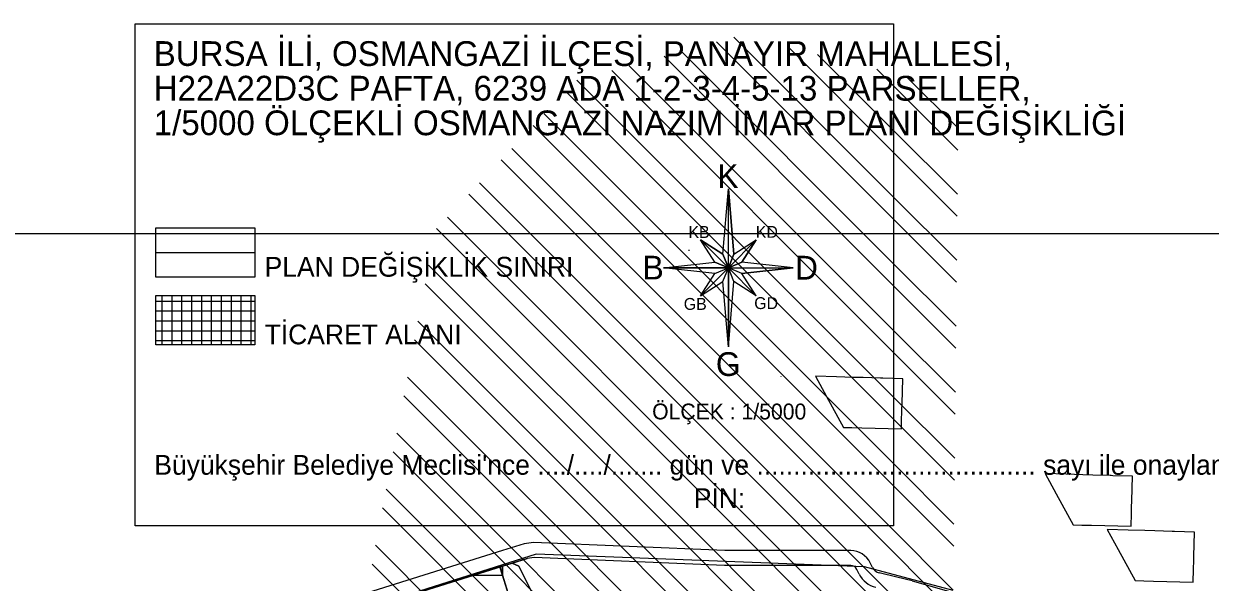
# Model space of a CAD drawing. Extents: x 409341 to 428634, y 4447481 to 4463281.
# Drawn here: x 420364 to 421563, y 4458529 to 4459094 of the extents above; entities that cross this region are included whole.
import ezdxf

# ---------------------------------------------------------------- set-up
doc = ezdxf.new("R2010")
doc.units = 0
for name, color, linetype in [('ADA', 7, 'Continuous'), ('ADAKENARI', 7, 'Continuous'), ('Default', 7, 'Continuous'), ('LJ_KUTU', 7, 'Continuous'), ('LJ_KUZEY', 7, 'Continuous'), ('LJ_SEMBOL', 7, 'Continuous'), ('LJ_YAZI', 7, 'Continuous'), ('OSB', 7, 'Continuous'), ('PL_AYA_PARK_DINLENME', 7, 'Continuous'), ('PL_K_TALI_IS_MRK', 7, 'Continuous'), ('PL_KON_ONE_250', 7, 'Continuous'), ('SN_ plan değişikliği', 7, 'Continuous'), ('SN_TR_SIVILASMA', 7, 'Continuous'), ('TR_ORTAGELISME', 7, 'Continuous'), ('TR_PARKALANI', 7, 'Continuous'), ('TR_TALIISMERK', 7, 'Continuous'), ('TR_YUKSEKYOGUNKONUT', 7, 'Continuous')]:
    doc.layers.add(name, color=color, linetype=linetype)

# ---------------------------------------------------------------- blocks, each defined once
blk = doc.blocks.new('POINT_DISPLAY')
at = {"layer": 'Default'}
blk.add_line((0, 0), (0, 0), dxfattribs=at)

msp = doc.modelspace()

# ---------------------------------------------------------------- linework, layer by layer
at = {"layer": 'ADA'}
msp.add_line((420844.7, 4458545.3), (420871.2, 4458460.8), dxfattribs=at)
at = {"layer": 'ADAKENARI'}
for p, q in [((420869.2, 4458568.3), (420847.5, 4458561.5)), ((420878.9, 4458569.6), (420869.2, 4458568.3)), ((421072.3, 4458561.4), (420878.9, 4458569.6)), ((420847.5, 4458561.5), (420577.1, 4458477)), ((420847.5, 4458545.8), (420872.4, 4458553.6)), ((420879.6, 4458554.5), (420872.4, 4458553.6)), ((421071.9, 4458546.4), (420879.6, 4458554.5)), ((421199.4, 4458561.4), (421072.3, 4458561.4)), ((420732.5, 4458509.8), (420847.5, 4458545.8)), ((421199.4, 4458546.4), (421071.9, 4458546.4)), ((421208, 4458537.7), (421205.7, 4458542.5)), ((421221.5, 4458544.3), (421219.2, 4458549.1)), ((421246.1, 4458534.7), (421228.2, 4458539)), ((421261.7, 4458531), (421246.1, 4458534.7)), ((421261.7, 4458531), (421303.1, 4458519))]:
    msp.add_line(p, q, dxfattribs=at)
for centre, radius, start, end in [((421199.4, 4458539.4), 22, 26.131, 90), ((421199.4, 4458539.4), 7, 26.131, 90), ((421230.5, 4458548.7), 10, 206.131, 256.6075), ((421230.5, 4458548.7), 25, 206.131, 256.6075)]:
    msp.add_arc(centre, radius, start, end, dxfattribs=at)
at = {"layer": 'Default'}
msp.add_lwpolyline([(428634.4, 4458881.4), (409341.5, 4458881.4)], dxfattribs=at)
for points in [[(421163.7, 4458737.6), (421174.9, 4458717.1), (421180.6, 4458706.8), (421192, 4458685.9), (421200.7, 4458685.7), (421210.7, 4458685.4), (421250.6, 4458684.5), (421250.7, 4458685.7), (421250.9, 4458696.3), (421251, 4458698.9), (421251.2, 4458704.7), (421251.3, 4458709), (421251.4, 4458710.2), (421252.2, 4458735), (421232, 4458735.6), (421230.5, 4458735.6), (421229.4, 4458735.7), (421211.9, 4458736.2), (421201.9, 4458736.5), (421185, 4458737)], [(421395.9, 4458639.2), (421407.1, 4458618.7), (421412.8, 4458608.4), (421424.3, 4458587.4), (421433, 4458587.2), (421442.9, 4458587), (421482.9, 4458586), (421482.9, 4458587.3), (421483.2, 4458597.9), (421483.3, 4458600.5), (421483.4, 4458606.3), (421483.6, 4458610.6), (421483.6, 4458611.7), (421484.4, 4458636.5), (421464.2, 4458637.1), (421462.8, 4458637.2), (421461.6, 4458637.2), (421444.1, 4458637.8), (421434.1, 4458638.1), (421417.2, 4458638.6)], [(421458.5, 4458582.9), (421469.7, 4458562.4), (421475.4, 4458552), (421486.9, 4458531.1), (421495.6, 4458530.9), (421505.5, 4458530.7), (421545.5, 4458529.7), (421545.5, 4458530.9), (421545.8, 4458541.5), (421545.9, 4458544.1), (421546.1, 4458550), (421546.2, 4458554.2), (421546.2, 4458555.4), (421547, 4458580.2), (421526.8, 4458580.8), (421525.4, 4458580.9), (421524.2, 4458580.9), (421506.7, 4458581.4), (421496.7, 4458581.7), (421479.8, 4458582.2)]]:
    msp.add_lwpolyline(points, close=True, dxfattribs=at)
at = {"layer": 'LJ_KUTU'}
for p, q in [((420497, 4458887.6), (420597, 4458887.6)), ((420497, 4458837.6), (420497, 4458887.6)), ((420597, 4458887.6), (420597, 4458837.6)), ((420597, 4458837.6), (420497, 4458837.6)), ((420497, 4458819.3), (420597, 4458819.3)), ((420497, 4458769.3), (420497, 4458819.3)), ((420597, 4458819.3), (420597, 4458769.3)), ((420597, 4458769.3), (420497, 4458769.3))]:
    msp.add_line(p, q, dxfattribs=at)
at = {"layer": 'LJ_SEMBOL'}
for p, q in [((421070.1, 4458860.8), (421075.8, 4458927)), ((421081.4, 4458860.8), (421075.8, 4458927)), ((421075.8, 4458847.1), (421047.5, 4458875.4)), ((421070.1, 4458860.8), (421047.5, 4458875.4)), ((421062.1, 4458852.8), (421047.5, 4458875.4)), ((421075.8, 4458847.1), (421104, 4458875.4)), ((421081.4, 4458860.8), (421104, 4458875.4)), ((421089.4, 4458852.8), (421104, 4458875.4)), ((421010.2, 4458847.1), (421062.1, 4458852.8)), ((421075.8, 4458847.1), (421062.1, 4458852.8)), ((421075.8, 4458847.1), (421070.1, 4458860.8)), ((421075.8, 4458847.1), (421081.4, 4458860.8)), ((421075.8, 4458847.1), (421089.4, 4458852.8)), ((421141.4, 4458847.1), (421089.4, 4458852.8)), ((421010.2, 4458847.1), (421075.8, 4458847.1)), ((421062.1, 4458841.5), (421010.2, 4458847.1)), ((421047.5, 4458818.9), (421075.8, 4458847.1)), ((421047.5, 4458818.9), (421062.1, 4458841.5)), ((421062.1, 4458841.5), (421075.8, 4458847.1)), ((421070.1, 4458833.5), (421075.8, 4458847.1)), ((421075.8, 4458847.1), (421141.4, 4458847.1)), ((421075.8, 4458767.2), (421075.8, 4458847.1)), ((421104, 4458818.9), (421075.8, 4458847.1)), ((421089.4, 4458841.5), (421075.8, 4458847.1)), ((421081.4, 4458833.5), (421075.8, 4458847.1)), ((421089.4, 4458841.5), (421141.4, 4458847.1)), ((421104, 4458818.9), (421089.4, 4458841.5)), ((421047.5, 4458818.9), (421070.1, 4458833.5)), ((421075.8, 4458767.2), (421070.1, 4458833.5)), ((421075.8, 4458767.2), (421081.4, 4458833.5)), ((421104, 4458818.9), (421081.4, 4458833.5))]:
    msp.add_line(p, q, dxfattribs=at)
for points in [[(421075.8, 4458927), (421081.4, 4458860.8), (421075.8, 4458847.1)], [(421047.5, 4458875.4), (421070.1, 4458860.8), (421075.8, 4458847.1)], [(421104, 4458875.4), (421089.4, 4458852.8), (421075.8, 4458847.1)], [(421062.1, 4458852.8), (421075.8, 4458847.1), (421010.2, 4458847.1)], [(421075.8, 4458847.1), (421047.5, 4458818.9), (421062.1, 4458841.5)], [(421075.8, 4458847.1), (421075.8, 4458767.2), (421070.1, 4458833.5)], [(421075.8, 4458847.1), (421141.4, 4458847.1), (421089.4, 4458841.5)], [(421075.8, 4458847.1), (421104, 4458818.9), (421081.4, 4458833.5)]]:
    msp.add_lwpolyline(points, close=True, dxfattribs=at)
at = {"layer": 'LJ_YAZI'}
msp.add_lwpolyline([(420476.1, 4459093.8), (421242.8, 4459093.8), (421242.8, 4458586.4), (420476.1, 4458586.4)], close=True, dxfattribs=at)
msp.add_lwpolyline([(420476.1, 4459093.8), (421242.8, 4459093.8), (421242.8, 4458586.4), (420476.1, 4458586.4)], close=True, dxfattribs=at)
msp.add_lwpolyline([(420476.1, 4459093.8), (421242.8, 4459093.8), (421242.8, 4458586.4), (420476.1, 4458586.4)], close=True, dxfattribs=at)
at = {"layer": 'OSB'}
msp.add_lwpolyline([(421303.1, 4458521), (421213.4, 4458545), (420881.6, 4458557.8), (420391.6, 4458402.7)], dxfattribs=at)
at = {"layer": 'PL_AYA_PARK_DINLENME'}
for p, q in [((420847.5, 4458545.8), (420844.9, 4458545)), ((420844.9, 4458545), (420847.5, 4458536.5)), ((420857.1, 4458548.8), (420847.5, 4458545.8)), ((420864.1, 4458545.8), (420857.1, 4458548.8)), ((420899.2, 4458474.8), (420864.1, 4458545.8)), ((420847.5, 4458536.5), (420871.2, 4458460.8))]:
    msp.add_line(p, q, dxfattribs=at)
for points in [[(420847.5, 4458545.8), (420847.5, 4458536.5)], [(420847.5, 4458536.5), (420847.5, 4458545.8)]]:
    msp.add_lwpolyline(points, dxfattribs=at)
at = {"layer": 'PL_K_TALI_IS_MRK'}
msp.add_lwpolyline([(420497, 4458819.3), (420597, 4458819.3), (420597, 4458769.3), (420497, 4458769.3)], close=True, dxfattribs=at)
at = {"layer": 'PL_KON_ONE_250'}
msp.add_line((421208, 4458537.7), (421205.7, 4458542.5), dxfattribs=at)
for points in [[(421199.4, 4458546.4), (421071.9, 4458546.4), (420879.6, 4458554.5), (420872.4, 4458553.6), (420857.1, 4458548.8), (420864.1, 4458545.8), (420899.2, 4458474.8), (420904.7, 4458463.7), (420914.6, 4458445.6)], [(420677.2, 4458364.6), (420677.3, 4458364.3), (420677.6, 4458363.4), (420703.7, 4458376.7), (420723.4, 4458386.7), (420743, 4458396.7), (420761.2, 4458405.9), (420784, 4458417.5), (420871.2, 4458460.8), (420847.5, 4458536.5), (420844.9, 4458545), (420732.5, 4458509.8), (420643.4, 4458482), (420659.5, 4458427.9), (420675.6, 4458370.4), (420677.2, 4458364.6)]]:
    msp.add_lwpolyline(points, dxfattribs=at)
for centre, radius, start, end in [((421199.4, 4458539.4), 7, 26.131, 90), ((421230.5, 4458548.7), 25, 206.131, 256.6075)]:
    msp.add_arc(centre, radius, start, end, dxfattribs=at)
at = {"layer": 'SN_ plan değişikliği'}
msp.add_line((420497, 4458862.6), (420597, 4458862.6), dxfattribs=at)
at = {"layer": 'SN_TR_SIVILASMA'}
for p, q in [((421242.8, 4458896.2), (421063.6, 4459075.4)), ((421242.8, 4458918.7), (421081.3, 4459080.3)), ((421242.8, 4458963.6), (421136.1, 4459070.3)), ((421242.8, 4458828.9), (421010.7, 4459061)), ((421242.8, 4458851.3), (421028.4, 4459065.8)), ((421242.8, 4458986), (421166, 4459062.8)), ((421242.8, 4458761.5), (420957.8, 4459046.5)), ((421242.8, 4458784), (420975.5, 4459051.3)), ((421242.8, 4459030.9), (421225.9, 4459047.8)), ((421242.8, 4458716.6), (420922.6, 4459036.9)), ((421308, 4458988.2), (421255.9, 4459040.3)), ((421242.8, 4458694.2), (420911.2, 4459025.8)), ((421307.8, 4458966), (421242.8, 4459030.9)), ((421242.8, 4458649.3), (420889.5, 4459002.7)), ((421242.8, 4458626.8), (420878.6, 4458991.1)), ((421307.3, 4458921.5), (421242.8, 4458986)), ((421238.3, 4458586.4), (420856.9, 4458967.9)), ((421307.1, 4458899.3), (421242.8, 4458963.6)), ((421215.9, 4458586.4), (420846, 4458956.3)), ((421171, 4458586.4), (420824.3, 4458933.1)), ((421148.5, 4458586.4), (420813.4, 4458921.5)), ((421306.6, 4458854.9), (421242.8, 4458918.7)), ((421103.6, 4458586.4), (420791.7, 4458898.4)), ((421306.4, 4458832.7), (421242.8, 4458896.2)), ((421081.2, 4458586.4), (420780.8, 4458886.8)), ((421036.3, 4458586.4), (420772.7, 4458850)), ((421305.9, 4458788.2), (421242.8, 4458851.3)), ((421013.8, 4458586.4), (420769.2, 4458831.1)), ((421305.7, 4458766), (421242.8, 4458828.9)), ((420968.9, 4458586.4), (420762, 4458793.3)), ((420968.9, 4458586.4), (420762, 4458793.3)), ((421305.2, 4458721.6), (421242.8, 4458784)), ((420946.5, 4458586.4), (420758.4, 4458774.5)), ((420946.5, 4458586.4), (420758.4, 4458774.5)), ((421305, 4458699.4), (421242.8, 4458761.5)), ((420901.6, 4458586.4), (420751.3, 4458736.7)), ((420879.1, 4458586.4), (420747.7, 4458717.8)), ((421304.5, 4458654.9), (421242.8, 4458716.6)), ((421304.3, 4458632.7), (421242.8, 4458694.2)), ((420822.7, 4458598), (420740.6, 4458680.1)), ((420800.2, 4458598), (420737, 4458661.2)), ((421303.8, 4458588.3), (421242.8, 4458649.3)), ((421303.6, 4458566), (421242.8, 4458626.8)), ((420755.3, 4458598), (420729.9, 4458623.4)), ((420732.9, 4458598), (420726.3, 4458604.5)), ((420744.4, 4458586.4), (420732.9, 4458598)), ((420766.9, 4458586.4), (420755.3, 4458598)), ((420811.8, 4458586.4), (420800.2, 4458598)), ((420834.2, 4458586.4), (420822.7, 4458598)), ((420847.5, 4458483.3), (420744.4, 4458586.4)), ((420847.5, 4458505.8), (420766.9, 4458586.4)), ((420847.5, 4458550.7), (420811.8, 4458586.4)), ((420847.5, 4458573.2), (420834.2, 4458586.4)), ((421299.4, 4458166.1), (420879.1, 4458586.4)), ((421299.7, 4458188.3), (420901.6, 4458586.4)), ((421300.1, 4458232.8), (420946.5, 4458586.4)), ((421300.1, 4458232.8), (420946.5, 4458586.4)), ((421300.4, 4458255), (420968.9, 4458586.4)), ((421300.4, 4458255), (420968.9, 4458586.4)), ((421300.8, 4458299.4), (421013.8, 4458586.4)), ((421301.1, 4458321.6), (421036.3, 4458586.4)), ((421301.5, 4458366.1), (421081.2, 4458586.4)), ((421301.8, 4458388.3), (421103.6, 4458586.4)), ((421302.2, 4458432.7), (421148.5, 4458586.4)), ((421302.5, 4458454.9), (421171, 4458586.4)), ((421302.9, 4458499.4), (421215.9, 4458586.4)), ((421303.1, 4458521.6), (421238.3, 4458586.4)), ((420847.5, 4458438.4), (420719.1, 4458566.8)), ((420976.9, 4458443.7), (420847.5, 4458573.2)), ((420847.5, 4458416), (420715.6, 4458547.9)), ((420953.8, 4458444.4), (420847.5, 4458550.7))]:
    msp.add_line(p, q, dxfattribs=at)
at = {"layer": 'TR_ORTAGELISME'}
for p, q in [((421208, 4458537.7), (421205.7, 4458542.5)), ((420818.3, 4458536.7), (420847.4, 4458536.7))]:
    msp.add_line(p, q, dxfattribs=at)
msp.add_lwpolyline([(421199.4, 4458546.4), (421071.9, 4458546.4), (420879.6, 4458554.5), (420872.4, 4458553.6), (420857.1, 4458548.8), (420864.1, 4458545.8), (420899.2, 4458474.8), (420904.7, 4458463.7), (420914.6, 4458445.6)], dxfattribs=at)
for centre, radius, start, end in [((421199.4, 4458539.4), 7, 26.131, 90), ((421230.5, 4458548.7), 25, 206.131, 256.6075)]:
    msp.add_arc(centre, radius, start, end, dxfattribs=at)
at = {"layer": 'TR_TALIISMERK'}
for p, q in [((420503.4, 4458769.3), (420503.4, 4458819.3)), ((420513.4, 4458769.3), (420513.4, 4458819.3)), ((420523.4, 4458769.3), (420523.4, 4458819.3)), ((420533.4, 4458769.3), (420533.4, 4458819.3)), ((420543.4, 4458769.3), (420543.4, 4458819.3)), ((420553.4, 4458769.3), (420553.4, 4458819.3)), ((420563.4, 4458769.3), (420563.4, 4458819.3)), ((420573.4, 4458769.3), (420573.4, 4458819.3)), ((420583.4, 4458769.3), (420583.4, 4458819.3)), ((420593.4, 4458769.3), (420593.4, 4458819.3)), ((420497, 4458813.6), (420597, 4458813.6)), ((420497, 4458803.6), (420597, 4458803.6)), ((420497, 4458793.6), (420597, 4458793.6)), ((420497, 4458783.6), (420597, 4458783.6)), ((420497, 4458773.6), (420597, 4458773.6))]:
    msp.add_line(p, q, dxfattribs=at)
at = {"layer": 'TR_YUKSEKYOGUNKONUT'}
for p, q in [((421036, 4458864.2), (421036, 4458865.2)), ((421129, 4458737.1), (421129, 4458737.3))]:
    msp.add_line(p, q, dxfattribs=at)

# ---------------------------------------------------------------- block references
at = {"layer": 'TR_PARKALANI', "xscale": 0.1, "yscale": 0.10000000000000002}
for p in [(420856.4, 4458546.4), (420852.8, 4458539.9), (420853.8, 4458531.8), (420857.5, 4458538.4), (420863, 4458535.2)]:
    msp.add_blockref('POINT_DISPLAY', p, dxfattribs=at)

# ---------------------------------------------------------------- texts
at = {"layer": 'LJ_KUZEY'}
msp.add_text('ÖLÇEK : 1/5000', height=16, rotation=359.9901, dxfattribs=at).set_placement((420998.7, 4458694))
at = {"layer": 'LJ_SEMBOL'}
for s, height, p in [('K', 24, (421064.6, 4458927.9)), ('KB', 12, (421035.4, 4458877.4)), ('KD', 12, (421103.5, 4458877.5)), ('B', 24, (420989, 4458835.4)), ('D', 24, (421143.1, 4458835.3)), ('GB', 12, (421030.7, 4458804.7)), ('GD', 12, (421101.9, 4458805.5)), ('G', 24, (421063.1, 4458737.9))]:
    msp.add_text(s, height=height, rotation=359.9901, dxfattribs=at).set_placement(p)
at = {"layer": 'LJ_YAZI'}
for s, p in [('BURSA İLİ, OSMANGAZİ İLÇESİ, PANAYIR MAHALLESİ,', (420494.9, 4459051.2)), ('H22A22D3C PAFTA, 6239 ADA 1-2-3-4-5-13 PARSELLER,', (420494.9, 4459016.2)), ('1/5000 ÖLÇEKLİ OSMANGAZİ NAZIM İMAR PLANI DEĞİŞİKLİĞİ', (420494.9, 4458981.2))]:
    msp.add_text(s, height=25, rotation=359.9901, dxfattribs=at).set_placement(p)
for s, p in [('PLAN DEĞİŞİKLİK SINIRI', (420607, 4458838.2)), ('TİCARET ALANI', (420607, 4458769.9)), ("Büyükşehir Belediye Meclisi'nce ..../..../....... gün ve ...................................... sayı ile onaylanmıştır.", (420495.5, 4458638.1)), ('PİN:', (421040.8, 4458604.4))]:
    msp.add_text(s, height=20, dxfattribs=at).set_placement(p)

doc.saveas('drawing.dxf')
